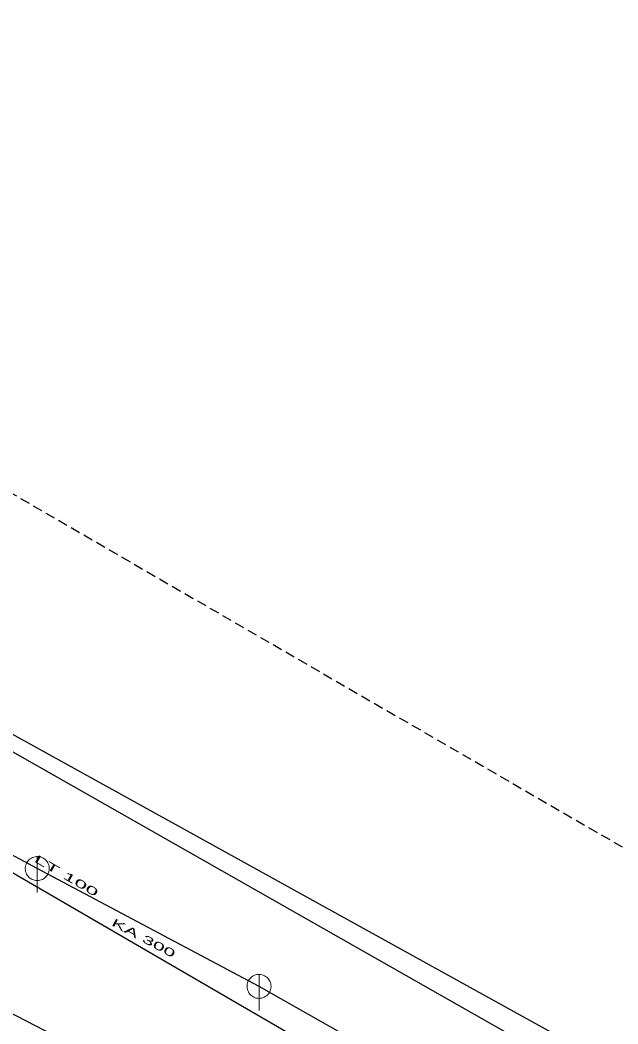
# Model space of a CAD drawing. Extents: x -687593 to -687108, y -975254 to -974717.
# Drawn here: x -687421.8 to -687372, y -974927.4 to -974843.8 of the extents above; entities that cross this region are included whole.
import ezdxf
from ezdxf.enums import TextEntityAlignment as Align

# ---------------------------------------------------------------- set-up
doc = ezdxf.new("R2010")
doc.units = 0
doc.header["$LTSCALE"] = 0.27
doc.linetypes.add('MEDIUM_DASHED', pattern=[4.5, 3, -1.5])
for name, color, linetype, lineweight in [('1', 7, 'Continuous', 25), ('14', 7, 'Continuous', 13), ('17', 7, 'Continuous', 25), ('22', 7, 'Continuous', 13), ('63', 7, 'MEDIUM_DASHED', 25)]:
    doc.layers.add(name, color=color, linetype=linetype, lineweight=lineweight)

msp = doc.modelspace()

# ---------------------------------------------------------------- linework, layer by layer
at = {"layer": '1'}
msp.add_lwpolyline([(-687190.553, -975166.941), (-687164.86, -975177.861), (-687155.924, -975158.837), (-687125.348, -975155.541), (-687124.826, -975139.621), (-687173.065, -975131.89), (-687231.828, -975028.025), (-687222.959, -975015.464), (-687237.898, -975004.026), (-687247.4, -975009.654), (-687276.892, -974983.781), (-687453.606, -974886.044), (-687460.232, -974860.45), (-687474.874, -974858.564), (-687482.889, -974882.272), (-687502.421, -974882.802), (-687499.452, -974907.164), (-687464.42, -974904.824), (-687331.319, -974973.728), (-687252.566, -975037.916), (-687192.379, -975151.48)], close=True, dxfattribs=at)
at = {"layer": '14', "lineweight": 25}
for p, q in [((-687420.363, -974914.448), (-687436.91, -974905.59)), ((-687401.895, -974924.263), (-687420.363, -974914.447))]:
    msp.add_line(p, q, dxfattribs=at)
msp.add_lwpolyline([(-687373.818, -974940.214), (-687392.845, -974929.413), (-687401.895, -974924.263)], dxfattribs=at)
at = {"layer": '17'}
for points in [[(-687435.81, -974897.134), (-687294.34, -974977.541), (-687214.33, -974877.654)], [(-687397.965, -974929.018), (-687440.137, -974904.525), (-687515.147, -974901.318)]]:
    msp.add_lwpolyline(points, dxfattribs=at)
at = {"layer": '22'}
for p, q in [((-687420.363, -974916.448), (-687420.362, -974913.448)), ((-687401.895, -974926.263), (-687401.894, -974923.263))]:
    msp.add_line(p, q, dxfattribs=at)
for points in [[(-687419.363, -974914.448), (-687419.368, -974914.339), (-687419.386, -974914.231), (-687419.416, -974914.125), (-687419.456, -974914.024), (-687419.508, -974913.927), (-687419.57, -974913.837), (-687419.642, -974913.754), (-687419.722, -974913.68), (-687419.81, -974913.614), (-687419.904, -974913.559), (-687420.004, -974913.514), (-687420.109, -974913.481), (-687420.216, -974913.459), (-687420.325, -974913.449), (-687420.435, -974913.451), (-687420.543, -974913.465), (-687420.65, -974913.49), (-687420.753, -974913.527), (-687420.851, -974913.576), (-687420.943, -974913.634), (-687421.029, -974913.703), (-687421.106, -974913.78), (-687421.175, -974913.866), (-687421.234, -974913.958), (-687421.282, -974914.056), (-687421.319, -974914.159), (-687421.345, -974914.266), (-687421.359, -974914.374), (-687421.362, -974914.484), (-687421.352, -974914.593), (-687421.331, -974914.7), (-687421.297, -974914.804), (-687421.253, -974914.904), (-687421.198, -974914.999), (-687421.132, -974915.087), (-687421.058, -974915.167), (-687420.975, -974915.239), (-687420.885, -974915.301), (-687420.789, -974915.353), (-687420.687, -974915.394), (-687420.582, -974915.424), (-687420.474, -974915.442), (-687420.364, -974915.448), (-687420.255, -974915.442), (-687420.147, -974915.424), (-687420.042, -974915.395), (-687419.94, -974915.354), (-687419.843, -974915.302), (-687419.753, -974915.24), (-687419.67, -974915.169), (-687419.595, -974915.089), (-687419.53, -974915.001), (-687419.474, -974914.907), (-687419.43, -974914.807), (-687419.396, -974914.703), (-687419.374, -974914.595), (-687419.364, -974914.486)], [(-687400.895, -974924.263), (-687400.9, -974924.154), (-687400.918, -974924.046), (-687400.948, -974923.94), (-687400.988, -974923.839), (-687401.04, -974923.742), (-687401.102, -974923.652), (-687401.174, -974923.569), (-687401.254, -974923.495), (-687401.342, -974923.429), (-687401.436, -974923.374), (-687401.536, -974923.329), (-687401.641, -974923.296), (-687401.748, -974923.274), (-687401.857, -974923.264), (-687401.967, -974923.266), (-687402.075, -974923.28), (-687402.182, -974923.305), (-687402.285, -974923.342), (-687402.383, -974923.391), (-687402.475, -974923.449), (-687402.561, -974923.518), (-687402.638, -974923.595), (-687402.707, -974923.681), (-687402.766, -974923.773), (-687402.814, -974923.871), (-687402.851, -974923.974), (-687402.877, -974924.081), (-687402.891, -974924.189), (-687402.894, -974924.299), (-687402.884, -974924.408), (-687402.863, -974924.515), (-687402.829, -974924.619), (-687402.785, -974924.719), (-687402.73, -974924.814), (-687402.664, -974924.902), (-687402.59, -974924.982), (-687402.507, -974925.054), (-687402.417, -974925.116), (-687402.321, -974925.168), (-687402.219, -974925.209), (-687402.114, -974925.239), (-687402.006, -974925.257), (-687401.896, -974925.263), (-687401.787, -974925.257), (-687401.679, -974925.239), (-687401.574, -974925.21), (-687401.472, -974925.169), (-687401.375, -974925.117), (-687401.285, -974925.055), (-687401.202, -974924.984), (-687401.127, -974924.904), (-687401.062, -974924.816), (-687401.006, -974924.722), (-687400.962, -974924.622), (-687400.928, -974924.518), (-687400.906, -974924.41), (-687400.896, -974924.301)]]:
    msp.add_lwpolyline(points, close=True, dxfattribs=at)
at = {"layer": '63'}
msp.add_lwpolyline([(-687526.998, -974914.677), (-687484.572, -974843.781), (-687484.572, -974843.781), (-687425.956, -974881.183), (-687425.956, -974881.183), (-687214.941, -975003.438), (-687214.941, -975003.438), (-687108.316, -975140.766), (-687108.316, -975140.766), (-687138.461, -975189.333), (-687138.461, -975189.333), (-687208.242, -975184.867), (-687208.242, -975184.867), (-687273.556, -975040.84), (-687273.556, -975040.84), (-687454.985, -974924.168), (-687454.985, -974924.168)], close=True, dxfattribs=at)

# ---------------------------------------------------------------- texts
at = {"layer": '1'}
for s, rotation, width, p in [('LT 100', 330, 2.15, (-687418.1007, -974915.3369)), ('LT 100', 330, 2.15, (-687418.1007, -974915.3369)), ('LT 100', 330, 2.15, (-687418.1007, -974915.3369)), ('LT 100', 330, 2.15, (-687418.1007, -974915.3369)), ('LT 100', 330, 2.15, (-687418.1007, -974915.3369)), ('KA 300', 332, 2, (-687411.6615, -974920.5337)), ('KA 300', 332, 2, (-687411.6615, -974920.5337)), ('KA 300', 332, 2, (-687411.6615, -974920.5337)), ('KA 300', 332, 2, (-687411.6615, -974920.5337)), ('KA 300', 332, 2, (-687411.6615, -974920.5337))]:
    msp.add_text(s, height=0.6667, rotation=rotation, dxfattribs=dict(at, width=width)).set_placement(p, align=Align.CENTER)

doc.saveas('drawing.dxf')
